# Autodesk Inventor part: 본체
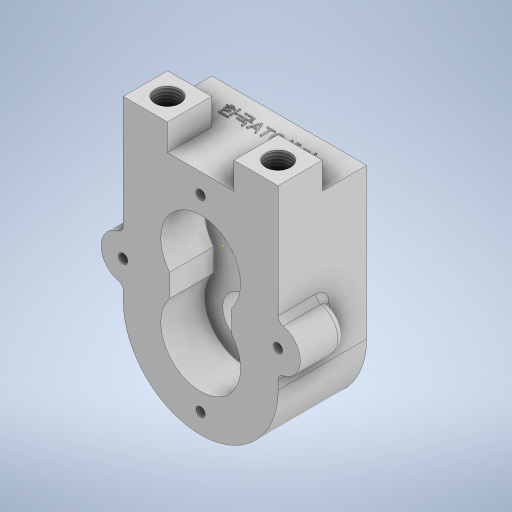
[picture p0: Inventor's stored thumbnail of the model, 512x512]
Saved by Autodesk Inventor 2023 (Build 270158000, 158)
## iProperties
Created: 2024-03
Part Number: 본체
Material: 일반
Document SubType Name: Modeling
Designer: asung
Density: 1 g/cm^3
Appearance: 기본값
Author: asung
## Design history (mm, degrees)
sketch "스케치1"
  geometry: L1 (-35, -34)-(35, -34); L2 (35, -34)-(35, 34); L3 (35, 34)-(-35, 34); L4 (-35, 34)-(-35, -34); L5 (-35, -34)-(35, 34); L6 (35, -34)-(-35, 34); C1 r 35 at (0, -34); 3 further points
  constraints: 12 end point, 3 midpoint, 2 parallel, 1 centre point, 1 horizontal, 1 perpendicular
  dimensions: "d0" = 70 distance of L3.end L2.end; "d1" = 68 distance of L2.end L1.end; "d2" = 70 diameter of C1
extrude "돌출1" new body sketch "스케치1" distance "d3" = 40; taper "d4" = 0 deg
sketch "스케치2"
  geometry: L1 (-35, 34)-(-35, -34) reference; L2 (35, -34)-(35, 34) reference; L3 (35, 34)-(-35, 34) reference; L4 (-35, 46)-(-15, 46); L5 (-15, 46)-(-15, 34); L6 (-15, 34)-(-35, 34); L7 (-35, 34)-(-35, 46); L8 (35, 34)-(15, 34); L9 (15, 34)-(15, 46); L10 (15, 46)-(35, 46); L11 (35, 46)-(35, 34); A1 r 35 centre (0, -34) between (-35, -34) and (35, -34) reference; 3 further points
  constraints: 16 end point, 4 parallel, 2 horizontal, 2 perpendicular
  dimensions: "d5" = 20 distance of L1.start L5.end; "d6" = 12 distance of L4.end L5.end; "d9" = 20 distance of L9.end L10.end; "d10" = 12 distance of L8.end L9.end
extrude "돌출2" join sketch "스케치2" distance "d11" = 20; taper "d12" = 0 deg
sketch "스케치3"
  geometry: L1 (-35, 46)-(-35, -34) reference; L2 (35, -34)-(35, 46) reference; L3 (35, 46)-(15, 46) reference; L4 (15, 46)-(15, 34) reference; L5 (15, 34)-(-15, 34) reference; L6 (-15, 34)-(-15, 46) reference; L7 (-15, 46)-(-35, 46) reference; L8 (-35, 46)-(-35, -17.5); L9 (35, 46)-(35, -17.5); C1 r 10 at (-35, -17.5); C2 r 10 at (35, -17.5); A1 r 35 centre (0, -34) between (-35, -34) and (35, -34) reference; 5 further points
  constraints: 4 end point, 2 centre point, 2 coincident, 2 point on line
  dimensions: "d13" = 63.5 distance of L1.start L8.end; "d14" = 10 radius of C1; "d15" = 63.5 distance of L2.end L9.end; "d16" = 10 radius of C2
extrude "돌출3" join sketch "스케치3" distance "d17" = 20; taper "d18" = 0 deg
fillet "모깎기1" dims "d19" = 3
fillet "모깎기2" dims "d20" = 3
sketch "스케치4"
  geometry: L1 (-35, 46)-(-35, -4.851) reference; L2 (-35, -30.149)-(-35, -34) reference; L3 (35, -34)-(35, -30.149) reference; L4 (35, -4.851)-(35, 46) reference; L5 (35, 46)-(15, 46) reference; L6 (15, 46)-(15, 34) reference; L7 (15, 34)-(-15, 34) reference; L8 (-15, 34)-(-15, 46) reference; L9 (-15, 46)-(-35, 46) reference; L10 (0, 34)-(0, -1); L11 (-14, -7.5)-(14, -7.5); L12 (14, -7.5)-(14, -27.5); L13 (14, -27.5)-(-14, -27.5); L14 (-14, -27.5)-(-14, -7.5); C1 r 18 at (0, -34); C2 r 18 at (0, -1); A1 r 3 centre (-38, -4.851) between (-37.308, -7.77) and (-35, -4.851) reference; A2 r 10 centre (-35, -17.5) between (-37.308, -7.77) and (-37.308, -27.23) reference; A3 r 3 centre (-38, -30.149) between (-35, -30.149) and (-37.308, -27.23) reference; A4 r 35 centre (0, -34) between (-35, -34) and (35, -34) reference; A5 r 3 centre (38, -30.149) between (37.308, -27.23) and (35, -30.149) reference; A6 r 10 centre (35, -17.5) between (37.308, -27.23) and (37.308, -7.77) reference; A7 r 3 centre (38, -4.851) between (35, -4.851) and (37.308, -7.77) reference; 7 further points
  constraints: 10 end point, 3 midpoint, 2 centre point, 2 coincident, 2 parallel, 1 horizontal, 1 horizontal alignment, 1 perpendicular, 1 vertical, 1 vertical alignment
  dimensions: "d22" = 36 diameter of C1; "d23" = 35 distance of L10.start L10.end; "d24" = 36 diameter of C2; "d25" = 28 distance of L12.end L13.end; "d26" = 20 distance of L11.end L12.end
extrude "돌출4" cut sketch "스케치4" distance "d27" = 20; taper "d28" = 0 deg
sketch "스케치7"
  geometry: 1 further point
sketch "스케치8"
  geometry: A1 r 18 centre (0, -34) between (-14, -22.686) and (14, -22.686) reference; 2 further points
  constraints: 1 coincident
hole "구멍2" sketch "스케치8" at (0, -34) diameter "d41" = 20; stored, may be unused: countersink angle "d45" = 90 deg, drill point angle "d47" = 0 deg; dims "d42" = 6, "d43" = 4, "d44" = 2, "d46" = 10
sketch "스케치9"
  geometry: L1 (34, 40)-(34, 0) reference; L2 (34, 0)-(-69, 0) reference; L3 (-24, 20)-(17, 20) reference; L4 (17, 20)-(17, 40) reference; L5 (17, 40)-(34, 40) reference; L6 (-69, 0)-(-69, 40) reference; L7 (-69, 40)-(-52, 40) reference; L8 (-52, 40)-(-52, 20) reference; L9 (-52, 20)-(-44, 20) reference; L10 (-44, 20)-(-44, 10) reference; L11 (-44, 10)-(-24, 10) reference; L12 (-24, 10)-(-24, 20) reference; L13 (34, 40)-(34, 0) reference; L14 (34, 0)-(-69, 0) reference; L15 (-24, 20)-(17, 20) reference; L16 (17, 20)-(17, 40) reference; L17 (17, 40)-(34, 40) reference; L18 (-69, 0)-(-69, 40) reference; L19 (-69, 40)-(-52, 40) reference; L20 (-52, 40)-(-52, 20) reference; L21 (-52, 20)-(-44, 20) reference; L22 (-44, 20)-(-44, 10) reference; L23 (-44, 10)-(-24, 10) reference; L24 (-24, 10)-(-24, 20) reference; L25 (-44, 20)-(-24, 20) reference; L26 (-24, 10)-(-44, 10) reference; L27 (-34, 20)-(-34, 5.959); L28 (-27, 10)-(-34, 5.959); L29 (-34, 5.959)-(-41, 10); 3 further points
  constraints: 6 end point, 2 point on line, 1 midpoint
  dimensions: "d49" = 14 diameter of L28.start L27; "d50" = 14 diameter of L29.end L27; "d51" = 120 deg angle of L29 L28; "d52" = 7 distance from line of L28.start L29
revolve "회전2" sketch "스케치9" stored, may be unused: angle "d53" = 90 deg
sketch "스케치10"
  geometry: 1 further point
sketch "스케치11"
  geometry: L1 (-14, -22.686)-(-14, -12.314) reference; L2 (14, -12.314)-(14, -22.686) reference; L3 (0, -1)-(0, 25); L4 (0, -34)-(0, -60); C1 r 10 at (0, -34) reference; A1 r 18 centre (0, -34) between (-14, -22.686) and (14, -22.686) reference; A2 r 18 centre (0, -1) between (14, -12.314) and (-14, -12.314) reference; 3 further points
  constraints: 4 end point, 2 coincident, 2 vertical
  dimensions: "d54" = 26 distance of L3.start L3.end; "d55" = 26 distance of L4.start L4.end
hole "구멍3" sketch "스케치11" at (0, 25), (0, -60) diameter "d56" = 4.134; stored, may be unused: countersink angle "d60" = 90 deg, drill point angle "d62" = 118 deg; dims "d57" = 10, "d58" = 4, "d59" = 2, "d61" = 12
sketch "스케치12"
  geometry: 1 further point
sketch "스케치13"
  geometry: 1 further point
sketch "스케치14"
  geometry: 1 further point
sketch "스케치15"
  geometry: L1 (35, 34)-(35, -34) reference; L2 (-35, 34)-(35, 34) reference; L3 (-35, -34)-(-35, 34) reference; L4 (0, 34)-(0, -1); C1 r 26 at (0, -1); C2 r 16 at (0, -1); A1 r 35 centre (0, -34) between (-35, -34) and (35, -34) reference; 1 further point
  constraints: 2 centre point, 2 coincident, 2 end point, 1 midpoint, 1 vertical
  dimensions: "d63" = 35 distance of L4.start L4.end; "d64" = 52 diameter of C1; "d65" = 32 diameter of C2
  node "투영된 루프9"
extrude "돌출5" join sketch "스케치15" distance "d66" = 6; taper "d67" = 0 deg
extrude "돌출6" join sketch "스케치15" distance "d68" = 10; taper "d69" = 0 deg
sketch "스케치16"
  geometry: 1 further point
fillet "모깎기3" dims "d70" = 3
sketch "스케치17"
  geometry: A1 r 18 centre (0, -1) between (14, -12.314) and (-14, -12.314) reference; 2 further points
  constraints: 1 coincident
hole "구멍4" sketch "스케치17" at (0, -1) diameter "d71" = 15; stored, may be unused: countersink angle "d75" = 90 deg, drill point angle "d77" = 0 deg; dims "d72" = 10, "d73" = 20, "d74" = 10, "d76" = 50
chamfer "모따기1" distance "d78" = 1; stored, may be unused: second distance "d79" = 2, angle "d80" = 45 deg
sketch "스케치18"
  geometry: L1 (25, 26.758)-(27.067, 28) reference; L2 (27.067, 28)-(27.067, 40) reference; L3 (27.067, 40)-(34, 40) reference; L4 (34, 40)-(34, 0) reference; L5 (34, 0)-(28, 0) reference; L6 (25, -3)-(25, -6) reference; L7 (25, -6)-(15, -6) reference; L8 (15, -6)-(15, -10) reference; L9 (15, -10)-(6.5, -10) reference; L10 (6.5, -10)-(6.5, 10) reference; L11 (6.5, 10)-(9, 10) reference; L12 (9, 10)-(9, 19) reference; L13 (9, 19)-(10, 20) reference; L14 (10, 20)-(17, 20) reference; L15 (17, 20)-(17, 40) reference; L16 (17, 40)-(22.933, 40) reference; L17 (22.933, 40)-(22.933, 28) reference; L18 (22.933, 28)-(25, 26.758) reference; L19 (-34, 5.959)-(-27, 10) reference; L20 (-27, 10)-(-24, 10) reference; L21 (-24, 10)-(-24, 20) reference; L22 (-24, 20)-(-12, 20) reference; L23 (-12, 20)-(-11, 19) reference; L24 (-11, 19)-(-11, 10) reference; L25 (-11, 10)-(-8.5, 10) reference; L26 (-8.5, 10)-(-8.5, -10) reference; L27 (-8.5, -10)-(-17, -10) reference; L28 (-17, -10)-(-17, -6) reference; L29 (-17, -6)-(-27, -6) reference; L30 (-27, -6)-(-27, -3) reference; L31 (-30, 0)-(-69, 0) reference; L32 (-69, 0)-(-69, 40) reference; L33 (-69, 40)-(-62.067, 40) reference; L34 (-62.067, 40)-(-62.067, 28) reference; L35 (-62.067, 28)-(-60, 26.758) reference; L36 (-60, 26.758)-(-57.933, 28) reference; L37 (-57.933, 28)-(-57.933, 40) reference; L38 (-57.933, 40)-(-52, 40) reference; L39 (-52, 40)-(-52, 20) reference; L40 (-52, 20)-(-44, 20) reference; L41 (-44, 20)-(-44, 10) reference; L42 (-44, 10)-(-41, 10) reference; L43 (-41, 10)-(-34, 5.959) reference; L44 (6.5, -10)-(-8.5, -10) reference; L45 (6.5, 10)-(-8.5, 10) reference; L46 (9, 10)-(-11, 10) reference; L47 (-11, 19)-(9, 19) reference; L48 (-1, -10)-(-1, 10); L49 (11.904, -10)-(11.5, -9.3); L50 (11.5, -9.3)-(11.5, -2.7); L51 (11.5, -2.7)-(-1, -2.7); A1 r 3 centre (28, -3) between (28, 0) and (25, -3) reference; A2 r 3 centre (-30, -3) between (-27, -3) and (-30, 0) reference; 2 further points
  constraints: 8 end point, 2 midpoint, 2 point on line, 1 perpendicular, 1 vertical
  dimensions: "d81" = 0.7 vertical distance of L49.start L49.end; "d82" = 7.3 vertical distance of L49.start L50.end; "d83" = 30 deg angle of L50 L49; "d84" = 25 diameter of L50 L48
revolve "회전3" sketch "스케치18" stored, may be unused: angle "d85" = 90 deg
chamfer "모따기2" distance "d86" = 1; stored, may be unused: second distance "d87" = 2, angle "d88" = 45 deg
sketch "스케치19"
  geometry: 1 further point
sketch "스케치20" dims "d89" = 42
  geometry: C1 r 26 at (0, 0) reference; C2 r 16 at (0, 0) reference; 3 further points
  constraints: 1 coincident, 1 vertical alignment, 2 other
hole "구멍5" sketch "스케치20" at (0, 21) diameter "d90" = 3.242; stored, may be unused: countersink angle "d94" = 90 deg, drill point angle "d96" = 118 deg; dims "d91" = 8, "d92" = 20, "d93" = 10, "d95" = 10
node "작업 평면1"
sketch "스케치23"
  geometry: L1 (20, 0)-(0, 0) reference; L2 (20, 0)-(20, 20) reference; L3 (0, 20)-(20, 20) reference; L4 (0, 0)-(0, 20) reference; L5 (70, 0)-(50, 0) reference; L6 (70, 0)-(70, 20) reference; L7 (50, 20)-(70, 20) reference; L8 (50, 0)-(50, 20) reference; 3 further points
  node "투영된 루프16"
  node "투영된 루프17"
sketch "스케치24"
  geometry: A1 r 10 centre (35, -17.5) between (37.308, -27.23) and (37.308, -7.77) reference; A2 r 10 centre (-35, -17.5) between (-37.308, -7.77) and (-37.308, -27.23) reference; 3 further points
  constraints: 2 coincident
hole "구멍7" sketch "스케치24" at (35, -17.5), (-35, -17.5) diameter "d109" = 4.134; stored, may be unused: countersink angle "d113" = 90 deg, drill point angle "d115" = 118 deg; dims "d110" = 10, "d111" = 4, "d112" = 2, "d114" = 12
sketch "스케치25"
  geometry: L1 (50, -40)-(20, -40) reference; L2 (70, 0)-(0, 0) reference; 3 further points
  constraints: 1 midpoint, 1 vertical alignment, 1 other
  dimensions: "d116" = 30 distance from line of L1 point (35, -10)
feature "엠보싱1" sketch "스케치25" dims "d9" = 20, "d10" = 12, "d117" = 0.5, "d118" = 0
hole "구멍8" sketch "스케치23" diameter "d119" = 10.5; stored, may be unused: countersink angle "d125" = 90 deg, drill point angle "d127" = 118 deg; dims "d120" = 11, "d121" = 0.62479, "d122" = 10.589, "d123" = 4, "d124" = 2, "d126" = 16
node "작업 평면2"
sketch "스케치27"
  geometry: 1 further point
node "솔리드1"
pattern_circular "원형 패턴1" dims angle "d98" = 360 deg
node "투영된 루프1"
node "투영된 루프2"
node "투영된 루프3"
node "투영된 루프7"
node "투영된 루프8"
node "투영된 루프10"
node "투영된 루프11"
node "투영된 루프12"
node "절단 모서리 투영2"
node "절단 모서리 투영3"
node "절단 모서리 투영4"
feature "A9D066F2-1C7D-4E18-AEED-F7BC21143FA4" dims "d41" = 20, "d42" = 6, "d43" = 4, "d44" = 2, "d45" = 90 deg, "d46" = 10, "d47" = 0
